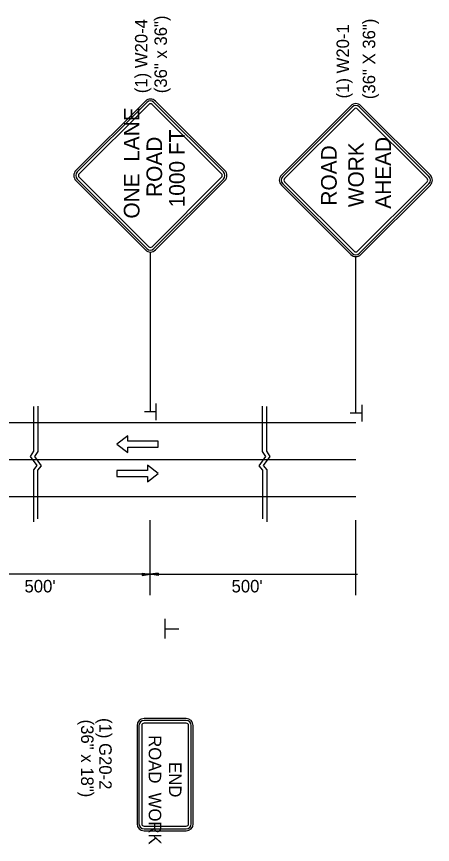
# Model space of a CAD drawing. Extents: x 1925873 to 1930787, y 596452 to 599617.
# Drawn here: x 1926127.7 to 1926327.5, y 596756.5 to 597154.6 of the extents above; entities that cross this region are included whole.
import ezdxf

# ---------------------------------------------------------------- set-up
doc = ezdxf.new("R2010")
doc.units = 0
for name, color, linetype in [('Default', 7, 'Continuous'), ('P_TC_Signs_Temporary', 7, 'Continuous'), ('R_Border', 7, 'Continuous'), ('R_Striping', 7, 'Continuous')]:
    doc.layers.add(name, color=color, linetype=linetype)

msp = doc.modelspace()

# ---------------------------------------------------------------- linework, layer by layer
at = {"layer": 'Default'}
for p, q in [((1926194.69, 596968.57), (1926194.69, 596960.56)), ((1926293.59, 596967.89), (1926293.59, 596959.89)), ((1926194.57, 596964.59), (1926189.11, 596964.59)), ((1926293.47, 596963.91), (1926288.01, 596963.91)), ((1925910.09, 596959.49), (1926290.74, 596959.46)), ((1925909.37, 596941.7), (1926290.74, 596941.67)), ((1925909.87, 596923.91), (1926290.74, 596923.88)), ((1926191.84, 596876.4), (1926191.84, 596912.43)), ((1926191.84, 596876.4), (1926191.84, 596912.43)), ((1926290.74, 596876.4), (1926290.74, 596912.43)), ((1926191.84, 596886.44), (1926092.08, 596886.44)), ((1926188, 596887.01), (1926191.84, 596886.44)), ((1926188, 596887.01), (1926188, 596885.86)), ((1926188, 596886.92), (1926191.2, 596886.44)), ((1926188, 596886.82), (1926190.54, 596886.44)), ((1926188, 596886.72), (1926189.9, 596886.44)), ((1926188, 596886.62), (1926189.25, 596886.44)), ((1926188, 596886.53), (1926188.61, 596886.44)), ((1926188, 596885.86), (1926191.84, 596886.44)), ((1926188, 596886.25), (1926189.25, 596886.44)), ((1926188, 596886.06), (1926190.54, 596886.44)), ((1926188, 596885.96), (1926191.2, 596886.44)), ((1926188, 596886.15), (1926189.9, 596886.44)), ((1926188, 596886.35), (1926188.61, 596886.44)), ((1926195.68, 596887.01), (1926191.84, 596886.44)), ((1926191.84, 596886.44), (1926291.6, 596886.44)), ((1926195.68, 596885.86), (1926191.84, 596886.44)), ((1926195.68, 596886.92), (1926192.48, 596886.44)), ((1926195.68, 596885.96), (1926192.48, 596886.44)), ((1926195.68, 596886.82), (1926193.14, 596886.44)), ((1926195.68, 596886.06), (1926193.14, 596886.44)), ((1926195.68, 596886.72), (1926193.78, 596886.44)), ((1926195.68, 596886.15), (1926193.78, 596886.44)), ((1926195.68, 596886.62), (1926194.43, 596886.44)), ((1926195.68, 596886.25), (1926194.43, 596886.44)), ((1926195.68, 596886.53), (1926195.07, 596886.44)), ((1926195.68, 596886.35), (1926195.07, 596886.44)), ((1926195.68, 596887.01), (1926195.68, 596885.86)), ((1926199.1, 596855.53), (1926199.1, 596865.02)), ((1926199.24, 596860.25), (1926205.72, 596860.25))]:
    msp.add_line(p, q, dxfattribs=at)
for points in [[(1926135.91, 596967.07), (1926135.91, 596945.55), (1926134.25, 596943.08), (1926137.49, 596938.65), (1926135.78, 596936.6), (1926135.78, 596911.58)], [(1926137.95, 596967.27), (1926137.95, 596945.46), (1926136.29, 596942.99), (1926139.53, 596938.56), (1926137.83, 596936.52), (1926137.82, 596913.01)], [(1926245.73, 596967.27), (1926245.73, 596945.46), (1926247.39, 596942.99), (1926244.15, 596938.56), (1926245.85, 596936.52), (1926245.86, 596913.01)], [(1926247.77, 596967.07), (1926247.77, 596945.55), (1926249.43, 596943.08), (1926246.19, 596938.65), (1926247.9, 596936.6), (1926247.9, 596911.58)]]:
    msp.add_lwpolyline(points, dxfattribs=at)
at = {"layer": 'P_TC_Signs_Temporary'}
for p, q in [((1926156.22, 597080.53), (1926189.63, 597113.94)), ((1926194.4, 597113.94), (1926227.81, 597080.53)), ((1926156.88, 597079.87), (1926190.29, 597113.28)), ((1926157.81, 597078.94), (1926191.22, 597112.35)), ((1926192.81, 597112.35), (1926226.22, 597078.94)), ((1926193.74, 597113.28), (1926227.15, 597079.87)), ((1926254.94, 597078.31), (1926288.35, 597111.72)), ((1926255.61, 597077.65), (1926289.02, 597111.06)), ((1926256.53, 597076.72), (1926289.94, 597110.13)), ((1926291.54, 597110.13), (1926324.95, 597076.72)), ((1926292.46, 597111.06), (1926325.87, 597077.65)), ((1926293.13, 597111.72), (1926326.54, 597078.31)), ((1926189.63, 597042.35), (1926156.22, 597075.76)), ((1926190.29, 597043.01), (1926156.88, 597076.42)), ((1926191.22, 597043.94), (1926157.81, 597077.35)), ((1926226.22, 597077.35), (1926192.81, 597043.94)), ((1926227.15, 597076.42), (1926193.74, 597043.01)), ((1926227.81, 597075.76), (1926194.4, 597042.35)), ((1926288.35, 597040.13), (1926254.94, 597073.54)), ((1926289.02, 597040.79), (1926255.61, 597074.2)), ((1926289.94, 597041.72), (1926256.53, 597075.13)), ((1926324.95, 597075.13), (1926291.54, 597041.72)), ((1926325.87, 597074.2), (1926292.46, 597040.79)), ((1926326.54, 597073.54), (1926293.13, 597040.13)), ((1926209.22, 596817.08), (1926188.97, 596817.08)), ((1926209.22, 596816.14), (1926188.97, 596816.14)), ((1926209.22, 596814.83), (1926188.97, 596814.83)), ((1926185.6, 596813.7), (1926185.6, 596766.45)), ((1926186.54, 596813.7), (1926186.54, 596766.45)), ((1926187.85, 596813.7), (1926187.85, 596766.45)), ((1926210.35, 596766.45), (1926210.35, 596813.7)), ((1926211.66, 596766.45), (1926211.66, 596813.7)), ((1926212.6, 596766.45), (1926212.6, 596813.7)), ((1926188.97, 596765.33), (1926209.22, 596765.33)), ((1926188.97, 596764.02), (1926209.22, 596764.02)), ((1926188.97, 596763.08), (1926209.22, 596763.08))]:
    msp.add_line(p, q, dxfattribs=at)
for centre, radius, start, end in [((1926192.01, 597111.56), 3.37, 45, 135), ((1926192.01, 597111.56), 2.44, 45, 135), ((1926192.01, 597111.56), 1.12, 45, 135), ((1926290.74, 597109.34), 3.38, 45, 135), ((1926290.74, 597109.34), 2.44, 45, 135), ((1926290.74, 597109.34), 1.12, 45, 135), ((1926158.6, 597078.15), 3.37, 135, 225), ((1926158.6, 597078.15), 2.44, 135, 225), ((1926158.6, 597078.15), 1.13, 135, 225), ((1926225.42, 597078.15), 1.13, 315, 45), ((1926225.42, 597078.15), 2.44, 315, 45), ((1926225.42, 597078.15), 3.37, 315, 45), ((1926257.33, 597075.93), 3.37, 135, 225), ((1926257.33, 597075.93), 2.44, 135, 225), ((1926324.15, 597075.93), 2.44, 315, 45), ((1926324.15, 597075.93), 3.37, 315, 45), ((1926257.33, 597075.93), 1.13, 135, 225), ((1926324.15, 597075.93), 1.13, 315, 45), ((1926192.01, 597044.73), 3.37, 225, 315), ((1926192.01, 597044.73), 2.44, 225, 315), ((1926192.01, 597044.73), 1.12, 225, 315), ((1926290.74, 597042.51), 1.12, 225, 315), ((1926290.74, 597042.51), 3.37, 225, 315), ((1926290.74, 597042.51), 2.44, 225, 315), ((1926188.97, 596813.7), 3.38, 90, 180), ((1926188.97, 596813.7), 2.44, 90, 180), ((1926188.97, 596813.7), 1.13, 90, 180), ((1926209.22, 596813.7), 3.37, 360, 90), ((1926209.22, 596813.7), 2.44, 360, 90), ((1926209.22, 596813.7), 1.13, 360, 90), ((1926188.97, 596766.45), 3.37, 180, 270), ((1926188.97, 596766.45), 2.44, 180, 270), ((1926188.97, 596766.45), 1.13, 180, 270), ((1926209.22, 596766.45), 2.44, 270, 360), ((1926209.22, 596766.45), 1.13, 270, 360), ((1926209.22, 596766.45), 3.38, 270, 360)]:
    msp.add_arc(centre, radius, start, end, dxfattribs=at)
at = {"layer": 'R_Border'}
for p, q in [((1926192.01, 596964.59), (1926192.01, 597041.36)), ((1926290.74, 596963.91), (1926290.74, 597039.14))]:
    msp.add_line(p, q, dxfattribs=at)
at = {"layer": 'R_Striping'}
for points in [[(1926181.11, 596953), (1926175.92, 596949), (1926181.11, 596945), (1926181.11, 596947.5), (1926195.82, 596947.5), (1926195.82, 596950.5), (1926181.11, 596950.5)], [(1926190.63, 596930.87), (1926195.82, 596934.87), (1926190.63, 596938.87), (1926190.63, 596936.37), (1926175.92, 596936.37), (1926175.92, 596933.37), (1926190.63, 596933.37)]]:
    msp.add_lwpolyline(points, close=True, dxfattribs=at)

# ---------------------------------------------------------------- texts
at = {"layer": 'Default'}
for s, rotation, p in [('(1) W20-1', 90, (1926287.46, 597115.21)), ('(36" X 36")', 90, (1926300.03, 597114.87)), ("500'", 359.9922, (1926131.52, 596877.71)), ("500'", 0.0078, (1926231.01, 596877.71))]:
    msp.add_text(s, height=6, rotation=rotation, dxfattribs=at).set_placement(p)
at = {"layer": 'P_TC_Signs_Temporary'}
for s, height, rotation, p in [('ONE  LANE', 7.5, 90, (1926186.76, 597057.45)), ('1000 FT', 7.5, 90, (1926208.51, 597062.85)), ('ROAD', 7.5, 90, (1926197.64, 597067.84)), ('WORK', 7.5, 90, (1926294.55, 597062.94)), (' AHEAD ', 7.5, 90, (1926307.57, 597059.38)), (' ROAD ', 7.5, 90, (1926281.53, 597060.9)), ('ROAD  WORK', 6, 270, (1926191.22, 596809.04)), ('END', 6, 270, (1926200.97, 596796.11))]:
    msp.add_text(s, height=height, rotation=rotation, dxfattribs=at).set_placement(p)
at = {"layer": 'R_Border'}
for s, height, rotation, p in [('(1) W20-4', 6, 90, (1926190.61, 597117.72)), ('(36" x 36")', 5.9996, 90, (1926199.97, 597117.72)), ('(36" x 18")', 5.9996, 270, (1926158.7, 596816.56)), ('(1) G20-2', 6, 270, (1926167.42, 596817.31))]:
    msp.add_text(s, height=height, rotation=rotation, dxfattribs=at).set_placement(p)

doc.saveas('drawing.dxf')
